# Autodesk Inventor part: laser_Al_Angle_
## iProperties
Shininess: 64.0
Length Units: 11272
Angle Units: 11279
Time Units: 11290
Mass Units: 11286
Length Display Precision: 3
Angle Display Precision: 2
Compacted: True
Part Number: laser_Al_Angle_
Document SubType Name: Modeling
Created: 2004-08
Designer: John Blackburn
Manufacturer: Standard
Standards Organization: Custom
Material: Aluminum-6061
Density: 0.0
Volumn: 0.0
Area: 0.0
PropertySet Name: Model Information
Control State: 0
Master: False
Checked Out: False
Author: John Blackburn
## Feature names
1. Extrusion1
2. Hole3
3. Hole4
